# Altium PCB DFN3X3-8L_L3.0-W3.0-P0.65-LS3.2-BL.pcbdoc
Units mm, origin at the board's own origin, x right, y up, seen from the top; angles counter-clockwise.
Board outline 17.2 x 15.76 mm, 2 copper layers (Top Layer, Bottom Layer), stack 0 mm thick; 1 components, 0 nets, 9 pads, 0 vias.
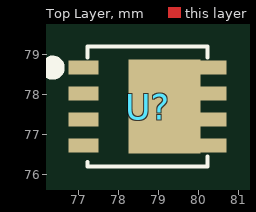
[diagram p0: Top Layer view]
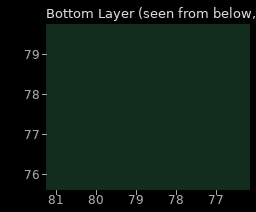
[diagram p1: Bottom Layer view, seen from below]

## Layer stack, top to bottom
Top Layer: signal copper (thickness not stored)
Bottom Layer: signal copper (thickness not stored)

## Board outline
87.049,69.85 69.85,69.85 69.85,85.612 87.049,85.612

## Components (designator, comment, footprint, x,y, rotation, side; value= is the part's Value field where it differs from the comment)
U? "" DFN3X3-8L_L3.0-W3.0-P0.65-LS3.2-BL 78.725,77.701 r0 top

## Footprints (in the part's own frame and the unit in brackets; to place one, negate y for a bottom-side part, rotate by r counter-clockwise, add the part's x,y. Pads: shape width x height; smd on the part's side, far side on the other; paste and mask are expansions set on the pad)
DFN3X3-8L_L3.0-W3.0-P0.65-LS3.2-BL [mm]
  rect 0.75x0.35 smd paste-100 mask+0.05: 1(-1.6,0.975) 2(-1.6,0.325) 3(-1.6,-0.325) 4(-1.6,-0.975) 5(1.6,-0.975) 6(1.6,-0.325) 7(1.6,0.325) 8(1.6,0.975)
  rect 1.8x2.35 smd paste-100 mask+0.05: 8(0.421,-0.001)
  silkscreen extent -2.52,-1.5 1.5,1.5

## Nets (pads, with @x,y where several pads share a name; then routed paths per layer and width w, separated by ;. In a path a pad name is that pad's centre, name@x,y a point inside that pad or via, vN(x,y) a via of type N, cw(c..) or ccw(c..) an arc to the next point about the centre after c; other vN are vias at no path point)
pads on no net: U?.1 U?.2 U?.3 U?.4 U?.5 U?.6 U?.7 U?.8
